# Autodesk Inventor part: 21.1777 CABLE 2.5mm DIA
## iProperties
Created: 2007-05
Part Number: 21.1777 CABLE 2.5mm DIA
Document SubType Name: Modeling
Designer: Andy Moles
Material: Steel
Mass: 2.89002 g
Surface Area: 5.98866 cm^2
Volume: 0.368155 cm^3
Density: 7.85 g/cm^3
Author: Andy Moles
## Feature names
1. Extrusion1
